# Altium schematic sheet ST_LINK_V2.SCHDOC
size A4; DocumentNumber: 2; Revision: D.1(PCB.SCH); SheetNumber: 2; SheetTotal: 6
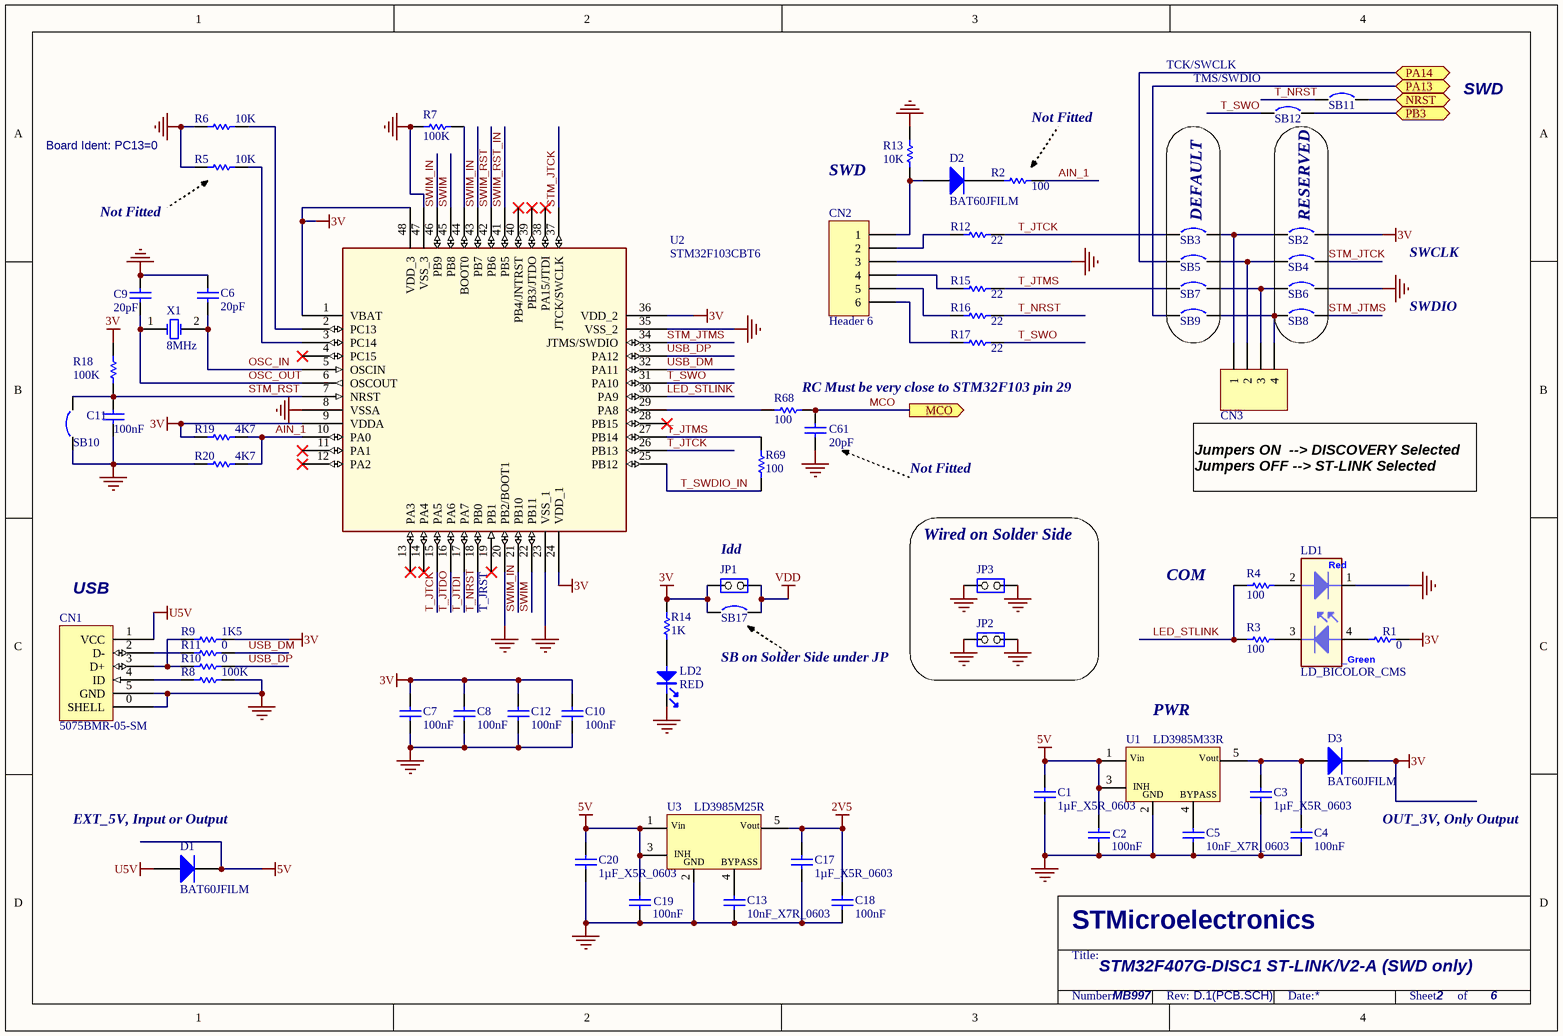
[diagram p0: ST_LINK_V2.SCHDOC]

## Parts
C1  1µF_X5R_0603  [0603C]
C2  100nF  [0603C]
C3  1µF_X5R_0603  [0603C]
C4  100nF  [0603C]
C5  10nF_X7R_0603  [0603C]
C6  20pF  [0402C]
C7  100nF  [0402C]
C8  100nF  [0402C]
C9  20pF  [0402C]
C10  100nF  [0402C]
C11  100nF  [0402C]
C12  100nF  [0402C]
C13  10nF_X7R_0603  [0603C]
C17  1µF_X5R_0603  [0603C]
C18  100nF  [0603C]
C19  100nF  [0603C]
C20  1µF_X5R_0603  [0603C]
C61  20pF  [0402C]
CN1  5075BMR-05-SM  [USB-MINI-B-SMD]
CN2  Header 6  [HDR1X6]
CN3  Header 4  [Header 4]  (value not drawn)
D1  BAT60JFILM  [SOD323/A]
D2  BAT60JFILM  [SOD323/A]
D3  BAT60JFILM  [SOD323/A]
JP1  (no value)  [SIP2/2.54]
JP2  (no value)  [SIP2/2.54]
JP3  (no value)  [SIP2/2.54]
LD1  LD_BICOLOR_CMS  [HSMF-A201]
LD2  RED  [0603D]
R1  0  [0402R]
R2  100  [0402R]
R3  100  [0402R]
R4  100  [0402R]
R5  10K  [0402R]
R6  10K  [0402R]
R7  100K  [0402R]
R8  100K  [0402R]
R9  1K5  [0402R]
R10  0  [0603R]
R11  0  [0603R]
R12  22  [0402R]
R13  10K  [0402R]
R14  1K  [0402R]
R15  22  [0402R]
R16  22  [0402R]
R17  22  [0402R]
R18  100K  [0402R]
R19  4K7  [0402R]
R20  4K7  [0402R]
R68  100  [0402R]
R69  100  [0402R]
SB2  Circuit Breaker  [JP2_SMD]  (value not drawn)
SB3  Circuit Breaker  [JP2_SMD]  (value not drawn)
SB4  Circuit Breaker  [JP2_SMD]  (value not drawn)
SB5  Circuit Breaker  [JP2_SMD]  (value not drawn)
SB6  Circuit Breaker  [JP2_SMD]  (value not drawn)
SB7  Circuit Breaker  [JP2_SMD]  (value not drawn)
SB8  Circuit Breaker  [JP2_SMD]  (value not drawn)
SB9  Circuit Breaker  [JP2_SMD]  (value not drawn)
SB10  Circuit Breaker  [JP2_SMD]  (value not drawn)
SB11  Circuit Breaker  [JP2_SMD]  (value not drawn)
SB12  Circuit Breaker  [JP2_SMD]  (value not drawn)
SB17  Circuit Breaker  [JP2_SMD]  (value not drawn)
U1  LD3985M33R  [SOT-23-5L]
U2  STM32F103CBT6  [QFP48 7x7]
U3  LD3985M25R  [SOT-23-5L]
X1  8MHz  [XTAL1]

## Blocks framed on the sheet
DEFAULT: SB3 SB5 SB7 SB9
RESERVED: SB2 SB4 SB6 SB8
Wired on Solder Side: JP2 JP3

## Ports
MCO (out), NRST, PA13, PA14, PB3

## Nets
2V5: C17.1 C18.2 U3.5(Vout)
3V: C7.2 C8.2 C10.2 C12.1 D3.2(K) JP1.1(COMMON) R1.2 R9.2 R14.2 R18.2 R19.1 SB2.2 SB17.1 U2.1(VBAT) U2.9(VDDA) U2.24(VDD_1) U2.36(VDD_2) U2.48(VDD_3)
5V: C1.2 C2.2 C19.2 C20.2 D1.2(K) U1.1(Vin) U1.3(CE) U3.1(Vin) U3.3(CE)
GND: C1.1 C2.1 C3.2 C4.1 C5.1 C6.1 C7.1 C8.1 C9.1 C10.1 C11.1 C12.2 C13.1 C17.2 C18.1 C19.1 C20.1 C61.2 CN1.0(SHELL) CN1.5(GND) CN2.3 JP2.1(COMMON) JP2.2(NO) JP3.1(COMMON) JP3.2(NO) LD1.1 LD2.2 R5.1 R6.1 R7.1 R8.2 R13.2 R20.1 SB6.2 SB10.1 U1.2(GND) U2.8(VSSA) U2.20(PB2/BOOT1) U2.23(VSS_1) U2.35(VSS_2) U2.47(VSS_3) U3.2(GND)
U5V: CN1.1(VCC) D1.1(A)
VDD: JP1.2(NO) SB17.2
AIN_1: R2.2 R19.2 R20.2 U2.10(PA0)
LED_STLINK: R3.1 R4.1 U2.30(PA9)
MCO: C61.1 R68.2 ; port MCO
NRST: SB11.2 ; port NRST
OSC_IN: C6.2 U2.5(OSCIN) X1.2(OSC2)
OSC_OUT: C9.2 U2.6(OSCOUT) X1.1(OSC1)
PA13: SB9.1 ; port PA13
PA14: SB5.1 ; port PA14
PB3: SB12.2 ; port PB3
STM_JTCK: SB4.2 U2.37(JTCK/SWCLK)
STM_JTMS: SB8.2 U2.34(JTMS/SWDIO)
STM_RST: C11.2 R18.1 SB10.2 U2.7(NRST)
SWIM: U2.22(PB11) U2.45(PB8)
SWIM_IN: U2.21(PB10) U2.43(PB7) U2.46(PB9)
SWIM_RST: U2.42(PB6)
SWIM_RST_IN: U2.41(PB5)
T_JTCK: R12.2 SB3.1 U2.15(PA5) U2.26(PB13)
T_JTDI: U2.17(PA7)
T_JTDO: U2.16(PA6)
T_JTMS: R15.2 R69.2 SB7.1 U2.27(PB14)
T_NRST: R16.2 SB11.1 U2.18(PB0)
T_SWDIO_IN: R69.1 U2.25(PB12)
T_SWO: R17.2 SB12.1 U2.31(PA10)
USB_DM: R11.2 U2.32(PA11)
USB_DP: R10.2 U2.33(PA12)
NetC3_1: C3.1 C4.2 D3.1(A) U1.5(Vout)
NetC5_2: C5.2 U1.4(BYPASS)
NetC13_2: C13.2 U3.4(BYPASS)
NetCN1_2: CN1.2(D-) R11.1
NetCN1_3: CN1.3(D+) R9.1 R10.1
NetCN1_4: CN1.4(ID) R8.1
NetCN2_1: CN2.1 D2.1(A) R13.1
NetCN2_2: CN2.2 R12.1
NetCN2_4: CN2.4 R15.1
NetCN2_5: CN2.5 R16.1
NetCN2_6: CN2.6 R17.1
NetCN3_1: CN3.1 SB2.1 SB3.2
NetCN3_2: CN3.2 SB4.1 SB5.2
NetCN3_3: CN3.3 SB6.1 SB7.2
NetCN3_4: CN3.4 SB8.1 SB9.2
NetD2_2: D2.2(K) R2.1
NetLD1_2: LD1.2 R4.2
NetLD1_3: LD1.3 R3.2
NetLD1_4: LD1.4 R1.1
NetLD2_1: LD2.1 R14.1
NetR5_2: R5.2 U2.3(PC14)
NetR6_2: R6.2 U2.2(PC13)
NetR7_2: R7.2 U2.44(BOOT0)
NetR68_1: R68.1 U2.29(PA8)

Not connected (* = marked no-connect by the designer): U2 4(PC15)* 11(PA1)* 12(PA2)* 13(PA3)* 14(PA4)* 19(PB1)* 28(PB15)* 38(PA15/JTDI)* 39(PB3/JTDO)* 40(PB4/JNTRST)*

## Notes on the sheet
- TCK/SWCLK
- (near SB12) TMS/SWDIO
- SWD
- Board Ident: PC13=0
- Not Fitted
- SWCLK
- SWDIO
- (near R68) RC Must be very close to STM32F103 pin 29
- Jumpers ON  --> DISCOVERY Selected
  Jumpers OFF --> ST-LINK Selected
- (near JP1) Idd
- COM
- (near CN1) USB
- (near U2) T_JRST
- SB on Solder Side under JP
- (near U1) PWR
- (near D1) EXT_5V, Input or Output
- OUT_3V, Only Output
- STM32F407G-DISC1 ST-LINK/V2-A (SWD only)
- MB997

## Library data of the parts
C1 C3 C17 C20 = CAP SMD 0603  X5R 1µF 25V 10%: 0603  X5R 1µF; Rated voltage: 25V; Tolerance: 10%
C2 C4 C6-C12 C18 C19 = Cap: Capacitor
C5 C13 = CAP SMD 0603  X7R 10000PF 50V 10%: 0603  X7R 10NF; Order code RS: 2040779; Rated voltage: 50V; Tolerance: 10%
C61 = Cap: Capacitor; Fitted: NO
CN1 = USB-MINI-typeB connector
CN2 = Header 6: Header, 6-Pin
CN3 = Header 4: Header, 4-Pin
D1-D3 = BAT60JFILM: Manuf_1: STM; Code - JEDEC: DO-214-AB; Provided: ST
JP1-JP3 = JP2
LD1 = LD_BICOLOR_CMS: Bicolor Led; Manuf_Part_1: HSMF-A201-A00J1; Manuf_1: Avago Technologies; Ref St: xxxxxx; cap_dec: ----
LD2 = PHOTO
R1 R3 R4 R6-R9 R12-R20 R68 R69 = res1: Resistor
R2 R5 = res1: Resistor; Fitted: NO
R10 R11 = res1: Resistor; Value: 10
SB2 SB4 SB6 SB8 SB11 SB12 SB17 = Circuit Breaker: Solder: YES
SB3 SB5 SB7 SB9 SB10 = Circuit Breaker: Solder: NO
U1 = LD3985M33R: Ultra low drop-low noise BiCMOS voltage, regulators low ESR capacitors compatible; Manuf_1: STM; Provided: ST
U2 = STM32F103CBT6: Medium-density performance line ARM-based 32-bit MCU with 128KB Flash; Manuf_1: STM; Ref St: xxxxxxxx; Provided: ST; ECCN_US/EU: 3A991A2/NEC
U3 = LD3985M25R: Ultra low drop-low noise BiCMOS voltage, regulators low ESR capacitors compatible; Manuf_1: STM; Provided: ST
X1 = XTAL: Crystal Oscillator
